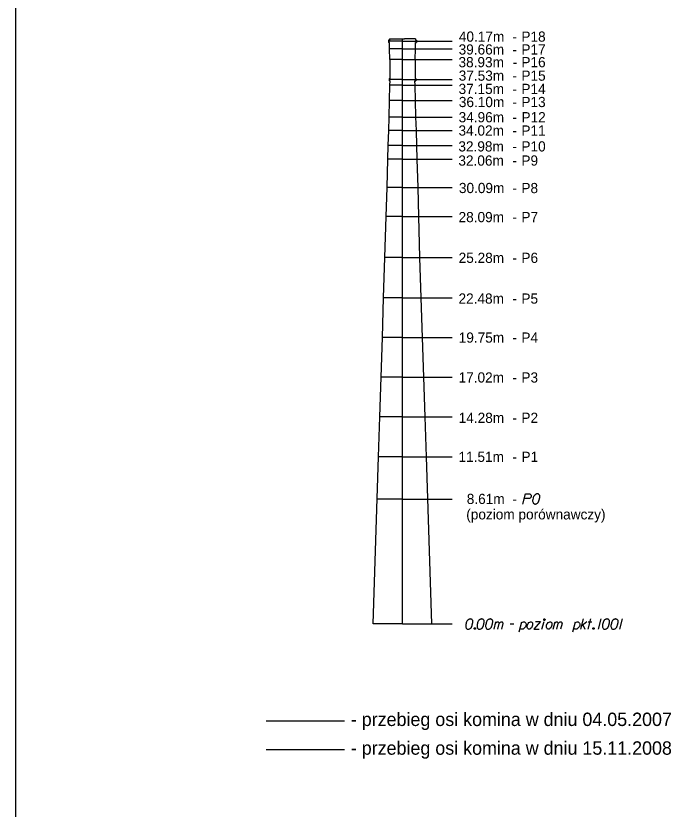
# Model space of a CAD drawing. Extents: x 138 to 264, y -75 to 121.
# Drawn here: x 196.41 to 206.33, y -57.33 to -45.34 of the extents above; entities that cross this region are included whole.
import ezdxf

# ---------------------------------------------------------------- set-up
doc = ezdxf.new("R2010")
doc.units = 0
for name, color, linetype in [('15 listopad 2008', 7, 'Continuous'), ('Opisy', 7, 'Continuous'), ('Ramka do drukowania', 7, 'Continuous')]:
    doc.layers.add(name, color=color, linetype=linetype)

msp = doc.modelspace()

# ---------------------------------------------------------------- linework, layer by layer
at = {"layer": '15 listopad 2008'}
for p, q in [((200.201, -55.997), (201.383, -55.997)), ((200.201, -56.429), (201.383, -56.429))]:
    msp.add_line(p, q, dxfattribs=at)
at = {"layer": 'Opisy'}
for p, q in [((202.049, -45.703), (202.049, -45.721)), ((202.066, -45.703), (202.049, -45.703)), ((202.066, -45.684), (202.066, -45.703)), ((202.066, -45.684), (202.293, -45.684)), ((202.262, -54.531), (202.262, -45.684)), ((202.458, -45.684), (202.293, -45.684)), ((202.458, -45.684), (202.458, -45.703)), ((202.458, -45.703), (202.475, -45.703)), ((202.475, -45.703), (202.475, -45.721)), ((202.262, -45.721), (202.049, -45.721)), ((202.049, -45.721), (202.049, -45.74)), ((202.066, -45.74), (202.049, -45.74)), ((202.066, -45.834), (202.066, -45.74)), ((202.262, -45.721), (203.015, -45.721)), ((202.458, -45.74), (202.475, -45.74)), ((202.458, -45.834), (202.458, -45.74)), ((202.475, -45.721), (202.475, -45.74)), ((202.262, -45.834), (202.066, -45.834)), ((202.072, -45.994), (202.066, -45.834)), ((202.262, -45.834), (203.015, -45.834)), ((202.452, -45.994), (202.458, -45.834)), ((202.262, -45.994), (202.072, -45.994)), ((202.072, -45.994), (202.072, -46.282)), ((202.262, -45.994), (203.015, -45.994)), ((202.452, -45.994), (202.452, -46.282)), ((202.059, -46.282), (202.059, -46.301)), ((202.059, -46.282), (202.072, -46.282)), ((202.262, -46.301), (202.059, -46.301)), ((202.059, -46.301), (202.059, -46.321)), ((202.262, -46.301), (203.015, -46.301)), ((202.465, -46.282), (202.452, -46.282)), ((202.465, -46.282), (202.465, -46.301)), ((202.465, -46.301), (202.465, -46.321)), ((202.074, -46.321), (202.059, -46.321)), ((202.066, -46.615), (202.072, -46.384)), ((202.072, -46.384), (202.074, -46.321)), ((202.262, -46.384), (202.072, -46.384)), ((202.262, -46.384), (203.015, -46.384)), ((202.452, -46.384), (202.45, -46.321)), ((202.45, -46.321), (202.465, -46.321)), ((202.458, -46.615), (202.452, -46.384)), ((202.059, -46.866), (202.066, -46.615)), ((202.262, -46.615), (202.066, -46.615)), ((202.262, -46.615), (203.015, -46.615)), ((202.465, -46.866), (202.458, -46.615)), ((202.053, -47.071), (202.059, -46.866)), ((202.262, -46.866), (202.059, -46.866)), ((202.262, -46.866), (203.015, -46.866)), ((202.472, -47.071), (202.465, -46.866)), ((202.047, -47.299), (202.053, -47.071)), ((202.262, -47.071), (202.053, -47.071)), ((202.262, -47.071), (203.015, -47.071)), ((202.477, -47.299), (202.472, -47.071)), ((202.04, -47.501), (202.047, -47.299)), ((202.262, -47.299), (202.047, -47.299)), ((202.262, -47.299), (203.015, -47.299)), ((202.485, -47.501), (202.477, -47.299)), ((202.028, -47.933), (202.04, -47.501)), ((202.262, -47.501), (202.04, -47.501)), ((202.262, -47.501), (203.015, -47.501)), ((202.497, -47.933), (202.485, -47.501)), ((202.014, -48.371), (202.028, -47.933)), ((202.262, -47.933), (202.028, -47.933)), ((202.262, -47.933), (203.015, -47.933)), ((202.51, -48.371), (202.497, -47.933)), ((201.997, -48.989), (202.014, -48.371)), ((202.262, -48.371), (202.014, -48.371)), ((202.262, -48.371), (203.015, -48.371)), ((202.527, -48.989), (202.51, -48.371)), ((201.977, -49.601), (201.997, -48.989)), ((202.262, -48.989), (201.997, -48.989)), ((202.262, -48.989), (203.015, -48.989)), ((202.547, -49.601), (202.527, -48.989)), ((201.958, -50.2), (201.977, -49.601)), ((202.262, -49.601), (201.977, -49.601)), ((202.262, -49.601), (203.015, -49.601)), ((202.566, -50.2), (202.547, -49.601)), ((201.94, -50.798), (201.958, -50.2)), ((202.262, -50.2), (201.958, -50.2)), ((202.262, -50.2), (203.015, -50.2)), ((202.584, -50.798), (202.566, -50.2)), ((201.921, -51.4), (201.94, -50.798)), ((202.262, -50.798), (201.94, -50.798)), ((202.262, -50.798), (203.015, -50.798)), ((202.603, -51.4), (202.584, -50.798)), ((201.901, -52.006), (201.921, -51.4)), ((202.262, -51.4), (201.921, -51.4)), ((202.262, -51.4), (203.015, -51.4)), ((202.623, -52.006), (202.603, -51.4)), ((201.819, -54.531), (201.901, -52.006)), ((202.262, -52.006), (201.901, -52.006)), ((202.262, -52.006), (203.015, -52.006)), ((202.705, -54.531), (202.623, -52.006)), ((202.262, -52.643), (201.881, -52.643)), ((202.262, -52.643), (203.015, -52.643)), ((202.262, -54.531), (201.819, -54.531)), ((202.262, -54.531), (203.015, -54.531))]:
    msp.add_line(p, q, dxfattribs=at)
for points in [[(204.084, -52.718), (204.126, -52.563), (204.178, -52.563), (204.185, -52.565), (204.189, -52.566), (204.196, -52.57), (204.201, -52.573), (204.205, -52.578), (204.208, -52.584), (204.211, -52.593), (204.212, -52.6), (204.211, -52.606), (204.209, -52.611), (204.207, -52.616), (204.205, -52.619), (204.201, -52.624), (204.196, -52.628), (204.192, -52.63), (204.186, -52.633), (204.18, -52.634), (204.107, -52.634)], [(204.305, -52.563), (204.303, -52.563), (204.296, -52.565), (204.291, -52.566), (204.287, -52.567), (204.281, -52.57), (204.274, -52.573), (204.268, -52.577), (204.262, -52.582), (204.258, -52.587), (204.254, -52.593), (204.251, -52.599), (204.247, -52.606), (204.245, -52.611), (204.242, -52.618), (204.239, -52.63), (204.235, -52.648), (204.232, -52.663), (204.232, -52.676), (204.234, -52.686), (204.239, -52.697), (204.242, -52.703), (204.248, -52.71), (204.256, -52.715), (204.259, -52.716), (204.266, -52.718), (204.273, -52.718), (204.282, -52.716), (204.291, -52.714), (204.297, -52.71), (204.305, -52.704), (204.309, -52.701), (204.314, -52.696), (204.317, -52.691), (204.32, -52.687), (204.322, -52.681), (204.324, -52.679), (204.326, -52.673), (204.328, -52.665), (204.331, -52.658), (204.332, -52.653), (204.333, -52.65), (204.334, -52.645), (204.337, -52.634), (204.338, -52.628), (204.339, -52.622), (204.341, -52.613), (204.342, -52.602), (204.342, -52.599), (204.341, -52.594), (204.339, -52.589), (204.336, -52.582), (204.332, -52.577), (204.328, -52.573), (204.324, -52.57), (204.319, -52.567), (204.315, -52.566), (204.311, -52.565), (204.305, -52.563)], [(203.291, -54.456), (203.289, -54.456), (203.282, -54.457), (203.277, -54.458), (203.273, -54.46), (203.267, -54.462), (203.26, -54.466), (203.254, -54.469), (203.248, -54.474), (203.244, -54.479), (203.24, -54.485), (203.237, -54.491), (203.233, -54.498), (203.231, -54.503), (203.228, -54.51), (203.225, -54.523), (203.221, -54.541), (203.219, -54.555), (203.219, -54.569), (203.22, -54.578), (203.225, -54.589), (203.228, -54.595), (203.234, -54.603), (203.242, -54.608), (203.245, -54.609), (203.253, -54.61), (203.259, -54.61), (203.268, -54.609), (203.277, -54.606), (203.283, -54.603), (203.291, -54.597), (203.295, -54.593), (203.3, -54.588), (203.304, -54.583), (203.306, -54.58), (203.308, -54.574), (203.31, -54.571), (203.312, -54.565), (203.315, -54.558), (203.317, -54.551), (203.318, -54.546), (203.319, -54.542), (203.321, -54.537), (203.323, -54.526), (203.324, -54.52), (203.325, -54.514), (203.327, -54.506), (203.328, -54.495), (203.328, -54.491), (203.327, -54.486), (203.325, -54.481), (203.322, -54.474), (203.318, -54.469), (203.315, -54.466), (203.31, -54.462), (203.305, -54.46), (203.301, -54.458), (203.298, -54.457), (203.291, -54.456)], [(203.463, -54.456), (203.46, -54.456), (203.453, -54.457), (203.448, -54.458), (203.444, -54.46), (203.438, -54.462), (203.431, -54.466), (203.425, -54.469), (203.419, -54.474), (203.415, -54.479), (203.412, -54.485), (203.408, -54.491), (203.404, -54.498), (203.402, -54.503), (203.399, -54.51), (203.396, -54.523), (203.392, -54.541), (203.39, -54.555), (203.39, -54.569), (203.391, -54.578), (203.396, -54.589), (203.399, -54.595), (203.406, -54.603), (203.413, -54.608), (203.416, -54.609), (203.424, -54.61), (203.43, -54.61), (203.44, -54.609), (203.448, -54.606), (203.454, -54.603), (203.463, -54.597), (203.466, -54.593), (203.471, -54.588), (203.475, -54.583), (203.477, -54.58), (203.48, -54.574), (203.481, -54.571), (203.483, -54.565), (203.486, -54.558), (203.488, -54.551), (203.489, -54.546), (203.491, -54.542), (203.492, -54.537), (203.494, -54.526), (203.495, -54.52), (203.497, -54.514), (203.498, -54.506), (203.499, -54.495), (203.499, -54.491), (203.498, -54.486), (203.497, -54.481), (203.493, -54.474), (203.489, -54.469), (203.486, -54.466), (203.481, -54.462), (203.476, -54.46), (203.472, -54.458), (203.469, -54.457), (203.463, -54.456)], [(203.592, -54.456), (203.59, -54.456), (203.583, -54.457), (203.578, -54.458), (203.574, -54.46), (203.568, -54.462), (203.561, -54.466), (203.555, -54.469), (203.549, -54.474), (203.545, -54.479), (203.541, -54.485), (203.538, -54.491), (203.534, -54.498), (203.532, -54.503), (203.529, -54.51), (203.526, -54.523), (203.522, -54.541), (203.52, -54.555), (203.52, -54.569), (203.521, -54.578), (203.526, -54.589), (203.529, -54.595), (203.535, -54.603), (203.543, -54.608), (203.546, -54.609), (203.554, -54.61), (203.56, -54.61), (203.569, -54.609), (203.578, -54.606), (203.584, -54.603), (203.592, -54.597), (203.596, -54.593), (203.601, -54.588), (203.605, -54.583), (203.607, -54.58), (203.609, -54.574), (203.611, -54.571), (203.613, -54.565), (203.616, -54.558), (203.618, -54.551), (203.619, -54.546), (203.62, -54.542), (203.622, -54.537), (203.624, -54.526), (203.625, -54.52), (203.626, -54.514), (203.628, -54.506), (203.629, -54.495), (203.629, -54.491), (203.628, -54.486), (203.626, -54.481), (203.623, -54.474), (203.619, -54.469), (203.616, -54.466), (203.611, -54.462), (203.606, -54.46), (203.602, -54.458), (203.599, -54.457), (203.592, -54.456)], [(204.407, -54.456), (204.413, -54.456), (204.417, -54.458), (204.42, -54.463), (204.42, -54.469), (204.417, -54.474), (204.413, -54.477), (204.407, -54.477), (204.403, -54.474), (204.4, -54.469), (204.4, -54.463), (204.403, -54.458), (204.407, -54.456)], [(204.963, -54.61), (205.004, -54.456)], [(205.071, -54.61), (205.111, -54.456)], [(205.266, -54.456), (205.225, -54.61)], [(205.36, -54.456), (205.357, -54.456), (205.35, -54.457), (205.345, -54.458), (205.342, -54.46), (205.336, -54.462), (205.328, -54.466), (205.322, -54.469), (205.316, -54.474), (205.313, -54.479), (205.309, -54.485), (205.305, -54.491), (205.302, -54.498), (205.299, -54.503), (205.297, -54.51), (205.293, -54.523), (205.29, -54.541), (205.287, -54.555), (205.287, -54.569), (205.288, -54.578), (205.293, -54.589), (205.297, -54.595), (205.303, -54.603), (205.31, -54.608), (205.314, -54.609), (205.321, -54.61), (205.327, -54.61), (205.337, -54.609), (205.345, -54.606), (205.351, -54.603), (205.36, -54.597), (205.364, -54.593), (205.368, -54.588), (205.372, -54.583), (205.374, -54.58), (205.377, -54.574), (205.378, -54.571), (205.381, -54.565), (205.383, -54.558), (205.385, -54.551), (205.387, -54.546), (205.388, -54.542), (205.389, -54.537), (205.391, -54.526), (205.393, -54.52), (205.394, -54.514), (205.395, -54.506), (205.396, -54.495), (205.396, -54.491), (205.395, -54.486), (205.394, -54.481), (205.39, -54.474), (205.387, -54.469), (205.383, -54.466), (205.378, -54.462), (205.373, -54.46), (205.37, -54.458), (205.366, -54.457), (205.36, -54.456)], [(205.49, -54.456), (205.487, -54.456), (205.48, -54.457), (205.475, -54.458), (205.472, -54.46), (205.465, -54.462), (205.458, -54.466), (205.452, -54.469), (205.446, -54.474), (205.442, -54.479), (205.439, -54.485), (205.435, -54.491), (205.432, -54.498), (205.429, -54.503), (205.427, -54.51), (205.423, -54.523), (205.419, -54.541), (205.417, -54.555), (205.417, -54.569), (205.418, -54.578), (205.423, -54.589), (205.427, -54.595), (205.433, -54.603), (205.44, -54.608), (205.444, -54.609), (205.451, -54.61), (205.457, -54.61), (205.467, -54.609), (205.475, -54.606), (205.481, -54.603), (205.49, -54.597), (205.493, -54.593), (205.498, -54.588), (205.502, -54.583), (205.504, -54.58), (205.507, -54.574), (205.508, -54.571), (205.51, -54.565), (205.513, -54.558), (205.515, -54.551), (205.516, -54.546), (205.518, -54.542), (205.519, -54.537), (205.521, -54.526), (205.523, -54.52), (205.524, -54.514), (205.525, -54.506), (205.526, -54.495), (205.526, -54.491), (205.525, -54.486), (205.524, -54.481), (205.52, -54.474), (205.516, -54.469), (205.513, -54.466), (205.508, -54.462), (205.503, -54.46), (205.499, -54.458), (205.496, -54.457), (205.49, -54.456)], [(205.588, -54.456), (205.547, -54.61)], [(203.649, -54.61), (203.677, -54.5)], [(203.67, -54.529), (203.676, -54.515), (203.682, -54.508), (203.69, -54.503), (203.697, -54.5), (203.702, -54.497), (203.709, -54.497), (203.711, -54.498), (203.716, -54.503), (203.721, -54.509), (203.725, -54.52), (203.726, -54.526), (203.732, -54.515), (203.739, -54.508), (203.747, -54.503), (203.754, -54.5), (203.76, -54.497), (203.766, -54.497), (203.771, -54.498), (203.775, -54.503), (203.778, -54.509), (203.782, -54.52), (203.783, -54.526), (203.762, -54.61)], [(203.705, -54.61), (203.726, -54.526)], [(203.892, -54.532), (203.945, -54.532)], [(204.027, -54.65), (204.068, -54.498)], [(204.065, -54.512), (204.077, -54.502), (204.095, -54.498), (204.11, -54.501), (204.119, -54.508), (204.127, -54.518), (204.132, -54.531), (204.133, -54.543), (204.13, -54.554), (204.127, -54.568), (204.117, -54.582), (204.105, -54.595), (204.087, -54.608), (204.071, -54.61), (204.056, -54.609), (204.04, -54.6)], [(204.201, -54.498), (204.209, -54.498), (204.219, -54.503), (204.229, -54.517), (204.23, -54.523), (204.231, -54.529), (204.231, -54.534), (204.231, -54.552), (204.227, -54.564), (204.221, -54.578), (204.214, -54.591), (204.202, -54.602), (204.191, -54.61), (204.173, -54.61), (204.166, -54.608), (204.158, -54.602), (204.155, -54.595), (204.15, -54.581), (204.15, -54.559), (204.152, -54.552), (204.157, -54.536), (204.162, -54.527), (204.164, -54.523), (204.176, -54.509), (204.189, -54.502), (204.201, -54.498)], [(204.274, -54.496), (204.352, -54.496), (204.252, -54.61), (204.329, -54.61)], [(204.373, -54.61), (204.405, -54.492)], [(204.492, -54.498), (204.501, -54.498), (204.51, -54.503), (204.52, -54.517), (204.521, -54.523), (204.522, -54.529), (204.522, -54.534), (204.522, -54.552), (204.519, -54.564), (204.513, -54.578), (204.505, -54.591), (204.493, -54.602), (204.482, -54.61), (204.464, -54.61), (204.457, -54.608), (204.45, -54.602), (204.446, -54.595), (204.441, -54.581), (204.441, -54.559), (204.443, -54.552), (204.448, -54.536), (204.453, -54.527), (204.456, -54.523), (204.468, -54.509), (204.48, -54.502), (204.492, -54.498)], [(204.543, -54.61), (204.571, -54.5)], [(204.564, -54.529), (204.57, -54.515), (204.576, -54.508), (204.583, -54.503), (204.59, -54.5), (204.595, -54.497), (204.602, -54.497), (204.605, -54.498), (204.61, -54.503), (204.615, -54.509), (204.618, -54.52), (204.619, -54.526), (204.626, -54.515), (204.633, -54.508), (204.64, -54.503), (204.647, -54.5), (204.653, -54.497), (204.66, -54.497), (204.664, -54.498), (204.668, -54.503), (204.672, -54.509), (204.675, -54.52), (204.677, -54.526), (204.656, -54.61)], [(204.599, -54.61), (204.619, -54.526)], [(204.84, -54.65), (204.882, -54.498)], [(204.878, -54.512), (204.89, -54.502), (204.908, -54.498), (204.923, -54.501), (204.933, -54.508), (204.94, -54.518), (204.945, -54.531), (204.946, -54.543), (204.944, -54.554), (204.94, -54.568), (204.93, -54.582), (204.918, -54.595), (204.9, -54.608), (204.884, -54.61), (204.87, -54.609), (204.854, -54.6)], [(204.978, -54.555), (205.05, -54.495)], [(204.992, -54.543), (205.024, -54.61)], [(205.071, -54.498), (205.129, -54.498)], [(203.356, -54.589), (203.362, -54.589), (203.365, -54.592), (203.369, -54.597), (203.369, -54.603), (203.365, -54.608), (203.362, -54.61), (203.356, -54.61), (203.352, -54.608), (203.348, -54.603), (203.348, -54.597), (203.352, -54.592), (203.356, -54.589)], [(205.15, -54.589), (205.156, -54.589), (205.16, -54.592), (205.163, -54.597), (205.163, -54.603), (205.16, -54.608), (205.156, -54.61), (205.15, -54.61), (205.146, -54.608), (205.143, -54.603), (205.143, -54.597), (205.146, -54.592), (205.15, -54.589)]]:
    msp.add_lwpolyline(points, dxfattribs=at)
at = {"layer": 'Ramka do drukowania'}
msp.add_line((196.41, -63.621), (196.41, -33.921), dxfattribs=at)

# ---------------------------------------------------------------- texts
at = {"layer": 'Opisy'}
for s, height, p in [('40.17m', 0.1542, (203.115, -45.727)), ('P18', 0.1542, (204.062, -45.727)), ('-', 0.154, (203.925, -45.727)), ('39.66m', 0.1542, (203.112, -45.921)), ('P17', 0.1542, (204.062, -45.921)), ('-', 0.154, (203.927, -45.921)), ('38.93m', 0.1542, (203.11, -46.113)), ('-', 0.154, (203.929, -46.113)), ('P16', 0.1542, (204.062, -46.113)), ('37.53m', 0.1542, (203.113, -46.317)), ('P15', 0.1542, (204.062, -46.317)), ('-', 0.154, (203.925, -46.317)), ('37.15m', 0.1542, (203.111, -46.518)), ('P14', 0.1542, (204.062, -46.518)), ('-', 0.154, (203.925, -46.518)), ('36.10m', 0.1542, (203.115, -46.716)), ('-', 0.154, (203.927, -46.716)), ('P13', 0.1542, (204.062, -46.716)), ('34.96m', 0.1542, (203.112, -46.946)), ('-', 0.154, (203.927, -46.946)), ('P12', 0.1542, (204.063, -46.946)), ('34.02m', 0.1542, (203.11, -47.147)), ('P11', 0.1542, (204.062, -47.147)), ('-', 0.154, (203.927, -47.147)), ('32.98m', 0.1542, (203.108, -47.387)), ('P10', 0.1542, (204.062, -47.387)), ('-', 0.154, (203.927, -47.387)), ('32.06m', 0.1542, (203.108, -47.601)), ('P9', 0.1542, (204.062, -47.601)), ('-', 0.154, (203.927, -47.601)), ('30.09m', 0.1542, (203.116, -48.016)), ('P8', 0.1542, (204.062, -48.017)), ('-', 0.154, (203.927, -48.016)), ('28.09m', 0.1542, (203.111, -48.456)), ('P7', 0.1542, (204.062, -48.456)), ('-', 0.154, (203.927, -48.456)), ('25.28m', 0.1542, (203.112, -49.072)), ('P6', 0.1542, (204.062, -49.072)), ('-', 0.154, (203.925, -49.072)), ('22.48m', 0.1542, (203.11, -49.688)), ('P5', 0.1542, (204.062, -49.688)), ('-', 0.154, (203.925, -49.688)), ('19.75m', 0.1542, (203.113, -50.278)), ('P4', 0.1542, (204.062, -50.278)), ('-', 0.154, (203.925, -50.278)), ('17.02m', 0.1542, (203.111, -50.881)), ('P3', 0.1542, (204.062, -50.881)), ('-', 0.154, (203.925, -50.881)), ('14.28m', 0.1542, (203.113, -51.491)), ('P2', 0.1542, (204.062, -51.491)), ('-', 0.154, (203.926, -51.491)), ('11.51m', 0.1542, (203.11, -52.081)), ('P1', 0.1542, (204.063, -52.081)), ('-', 0.154, (203.925, -52.081)), ('8.61m', 0.1542, (203.235, -52.718)), ('-', 0.154, (203.925, -52.718)), ('(poziom porównawczy)', 0.15416, (203.227, -52.951)), ('- przebieg osi komina w dniu 04.05.2007', 0.2024, (201.48, -56.075)), ('- przebieg osi komina w dniu 15.11.2008', 0.2024, (201.48, -56.509))]:
    msp.add_text(s, height=height, dxfattribs=at).set_placement(p)

doc.saveas('drawing.dxf')
